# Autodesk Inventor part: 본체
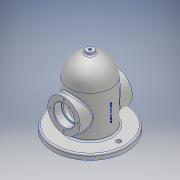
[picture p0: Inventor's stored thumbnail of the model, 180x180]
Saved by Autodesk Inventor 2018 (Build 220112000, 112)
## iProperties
Created: 2019-11
Part Number: 본체
Material: 알루미늄 6061
Document SubType Name: Modeling
Designer: CAD
Density: 2.7 g/cm^3
Appearance: 알루미늄 - 평지
Mass: 1106.08 g
Surface Area: 882.769 cm^2
Volume: 409.661 cm^3
Author: CAD
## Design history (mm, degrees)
sketch "스케치1"
  geometry: C1 r 70 at (0, 0); 1 further point
  constraints: 1 centre point, 1 coincident
  dimensions: "d0" = 140 diameter of C1
extrude "돌출1" new body sketch "스케치1" distance "d1" = 10; taper "d2" = 0 deg
sketch "스케치2"
  geometry: C1 r 40 at (0, 0); 1 further point
  constraints: 1 centre point, 1 coincident
  dimensions: "d3" = 80 diameter of C1
extrude "돌출2" join sketch "스케치2" distance "d4" = 80; taper "d5" = 0 deg
sketch "스케치3"
  geometry: L1 (0, 40)-(0, -40); C1 r 40 at (0, 0) reference; A1 r 40 centre (0, 0) between (0, 40) and (0, -40) reference; A2 r 40 centre (0, 0) between (0, -40) and (0, 40); 2 further points
  constraints: 4 point on circle, 2 coincident, 2 end point, 1 centre point, 1 midpoint, 1 vertical
revolve "회전1" sketch "스케치3" stored, may be unused: angle "d6" = 90 deg
node "작업 평면2"
  node "작업 평면1"
sketch "스케치4"
  geometry: 1 further point
sketch "스케치5"
  geometry: L1 (-70, 0)-(70, 0) reference; L2 (-70, 50)-(70, 50); L3 (0, 0)-(0, 161.96); C1 r 31 at (0, 50)
  constraints: 4 end point, 1 centre point, 1 midpoint, 1 parallel, 1 point on line, 1 vertical
  dimensions: "d9" = 50 distance between parallel lines of L1 L2; "d10" = 62 diameter of C1
extrude "돌출3" join sketch "스케치5" distance "d11" = 100; taper "d12" = 0 deg
node "작업 평면4"
sketch "스케치6"
  geometry: C1 r 7.5 at (0, 0); 1 further point
  constraints: 1 centre point, 1 coincident
  dimensions: "d15" = 15 diameter of C1
extrude "돌출4" join sketch "스케치6" distance "d16" = 15; taper "d17" = 0 deg
sketch "스케치7"
  geometry: 2 further points
  constraints: 1 coincident
hole "구멍1" sketch "스케치7" at (0, 0) diameter "d18" = 5.188; stored, may be unused: countersink angle "d22" = 90 deg, drill point angle "d24" = 118 deg; dims "d19" = 12, "d20" = 4, "d21" = 2, "d23" = 16
sketch "스케치8"
  geometry: C1 r 31 at (0, 0) reference; C2 r 16.5 at (0, 0); 1 further point
  constraints: 1 centre point, 1 coincident
  dimensions: "d25" = 33 diameter of C2
extrude "돌출5" cut sketch "스케치8" extent not by distance; stored distance "d26" = 15; taper "d27" = 0 deg
sketch "스케치9"
  geometry: C1 r 31 at (0, 0) reference; C2 r 20 at (0, 0); 1 further point
  constraints: 1 centre point, 1 coincident
  dimensions: "d28" = 40 diameter of C2
extrude "돌출6" cut sketch "스케치9" distance "d29" = 15; taper "d30" = 0 deg
sketch "스케치10"
  geometry: C1 r 2.594 at (0, 0) reference; C2 r 30 at (0, 0); 1 further point
  constraints: 1 centre point, 1 coincident
  dimensions: "d31" = 60 diameter of C2
extrude "돌출7" cut sketch "스케치10" distance "d32" = 90; taper "d33" = 0 deg
sketch "스케치11"
  geometry: L1 (0, 30)-(0, -30); C1 r 7.5 at (0, 0) reference; A1 r 30 centre (0, 0) between (0, -30) and (0, 30); A2 r 30 centre (0, 0) between (0, 30) and (0, -30) reference; 1 further point
  constraints: 3 point on circle, 2 end point, 1 centre point, 1 coincident
revolve "회전2" sketch "스케치11" stored, may be unused: angle "d34" = 90 deg
chamfer "모따기1" distance "d35" = 1; stored, may be unused: second distance "d36" = 2, angle "d37" = 45 deg
fillet "모깎기1" dims "d38" = 0.3
fillet "모깎기2" dims "d39" = 3
sketch "스케치12" dims "d41" = 52
  geometry: L1 (0, 0)-(0, 26); C1 r 16.5 at (0, 0) reference; C2 r 21 at (0, 0) reference; 3 further points
  constraints: 2 coincident, 2 end point, 1 vertical, 1 vertical alignment, 2 other
hole "구멍2" sketch "스케치12" at (0, 26) diameter "d42" = 3.242; stored, may be unused: countersink angle "d46" = 90 deg, drill point angle "d48" = 118 deg; dims "d43" = 8, "d44" = 4, "d45" = 2, "d47" = 10
sketch "스케치13"
  geometry: L1 (0, 0)-(-55, 0); C1 r 2.594 at (0, 0) reference; A1 r 55 centre (0, 0) between (-55, 0) and (55, 0); 3 further points
  constraints: 3 coincident, 2 end point, 2 point on circle, 1 centre point, 1 horizontal
  dimensions: "d52" = 110 diameter of A1
hole "구멍3" sketch "스케치13" at (-55, 0), (55, 0) diameter "d53" = 9; stored, may be unused: countersink angle "d57" = 90 deg, drill point angle "d59" = 118 deg; dims "d54" = 8, "d55" = 4, "d56" = 2, "d58" = 10
sketch "스케치14"
  geometry: 1 further point
node "작업 평면6"
sketch "스케치16"
  geometry: L1 (-70, 0)-(70, 0) reference; L2 (0, 0)-(0, 153.215); 1 further point
  constraints: 2 end point, 1 point on line, 1 vertical, 1 other
  dimensions: "d62" = 50 distance from line of L1 point (0, 50)
feature "엠보싱1" sketch "스케치16" dims "d63" = 0.5, "d64" = 0
node "솔리드1"
mirror "미러1"
pattern_circular "원형 패턴1" dims angle "d50" = 360 deg
mirror "미러2"
node "투영된 루프1"
node "투영된 루프2"
other parameters: "d14" = -135
